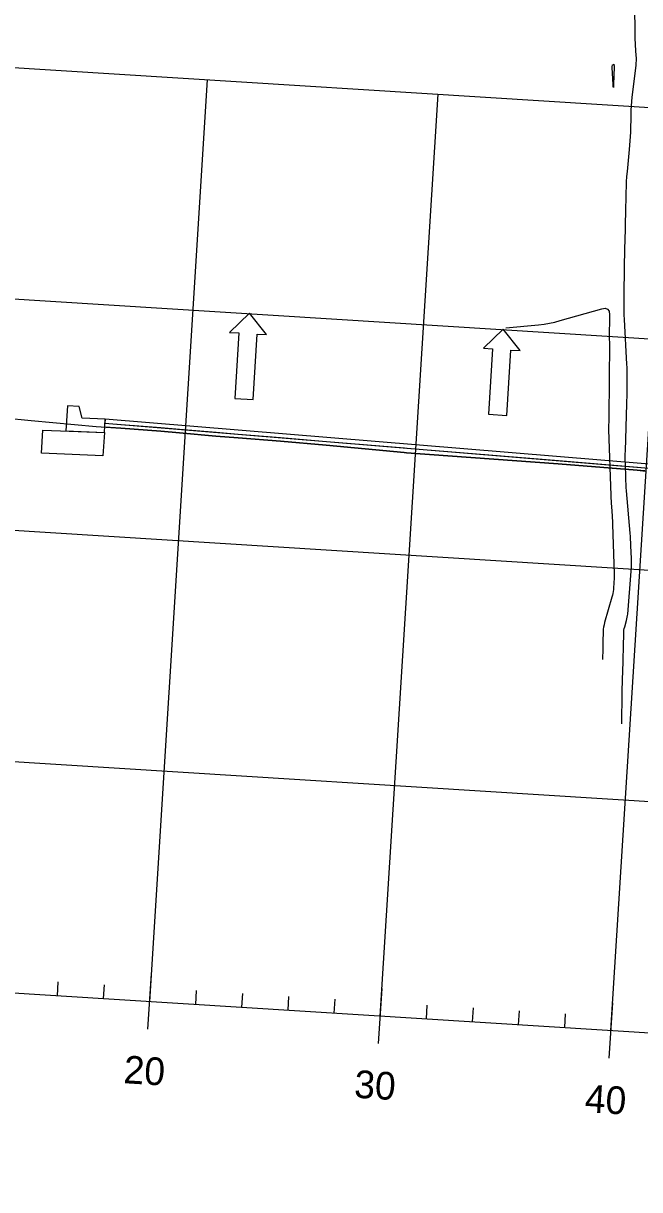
# Model space of a CAD drawing. Extents: x 658976 to 668726, y 639543 to 647196.
# Drawn here: x 661223.2 to 661356.5, y 641900.6 to 642153.2 of the extents above; entities that cross this region are included whole.
import ezdxf

# ---------------------------------------------------------------- set-up
doc = ezdxf.new("R2010")
doc.units = 0
for name, color, linetype in [('Ex_Minor Contours', 7, 'Continuous'), ('R_Axis', 7, 'Continuous'), ('R_Axis Annot', 7, 'Continuous'), ('R_Exist Surface', 7, 'Continuous'), ('R_Fin Surface', 7, 'Continuous'), ('R_Grid', 7, 'Continuous'), ('R_MOT', 7, 'Continuous'), ('R_Proposed Const Limits', 7, 'Continuous')]:
    doc.layers.add(name, color=color, linetype=linetype)

msp = doc.modelspace()

# ---------------------------------------------------------------- linework, layer by layer
msp.add_lwpolyline([(661240.88, 642067.45), (661235.89, 642067.67), (661235.21, 642070.22), (661232.71, 642070.37), (661232.37, 642064.9), (661240.7, 642064.54)], close=True)
at = {"layer": 'Ex_Minor Contours'}
for points in [[(661352.64, 642001.45), (661352.75, 642008.09), (661352.77, 642009.2), (661352.79, 642010.3), (661352.82, 642011.41), (661352.85, 642012.52), (661353.06, 642021.04), (661353.08, 642021.4), (661353.12, 642021.76), (661353.19, 642022.11), (661353.28, 642022.46), (661353.68, 642023.85), (661353.77, 642024.2), (661353.84, 642024.55), (661353.9, 642024.91), (661353.94, 642025.26), (661354.67, 642034.55), (661354.72, 642035.23), (661354.74, 642035.92), (661354.75, 642036.6), (661354.73, 642037.29), (661354.63, 642040.03), (661354.61, 642040.72), (661354.57, 642041.4), (661354.52, 642042.08), (661354.47, 642042.77), (661353.68, 642051.97), (661353.63, 642052.69), (661353.58, 642053.41), (661353.54, 642054.12), (661353.52, 642054.84), (661353.43, 642057.71), (661353.41, 642058.43), (661353.4, 642059.15), (661353.41, 642059.87), (661353.43, 642060.59), (661353.76, 642070.81), (661353.78, 642071.53), (661353.8, 642072.24), (661353.81, 642072.95), (661353.81, 642073.67), (661353.83, 642076.52), (661353.83, 642077.23), (661353.82, 642077.95), (661353.8, 642078.66), (661353.77, 642079.37), (661353.24, 642089.05), (661353.19, 642090.03), (661353.17, 642091), (661353.15, 642091.97), (661353.16, 642092.94), (661353.2, 642096.84), (661353.21, 642097.81), (661353.23, 642098.79), (661353.25, 642099.76), (661353.27, 642100.73), (661353.41, 642106.9), (661353.43, 642108.1), (661353.46, 642109.29), (661353.49, 642110.49), (661353.51, 642111.69), (661353.61, 642116.65), (661353.64, 642117.76), (661353.7, 642118.87), (661353.78, 642119.98), (661353.87, 642121.09), (661354.35, 642125.84), (661354.43, 642126.78), (661354.5, 642127.73), (661354.55, 642128.67), (661354.58, 642129.62), (661354.66, 642133.41), (661354.69, 642134.36), (661354.74, 642135.3), (661354.82, 642136.25), (661354.92, 642137.19), (661355.73, 642144.01), (661355.78, 642144.56), (661355.81, 642145.12), (661355.81, 642145.67), (661355.79, 642146.23), (661355.64, 642148.45), (661355.6, 642149), (661355.58, 642149.56), (661355.56, 642150.11), (661355.55, 642150.67), (661355.48, 642157.23)], [(661327.56, 642087.27), (661334.66, 642087.92), (661335.84, 642088.06), (661337, 642088.25), (661338.16, 642088.49), (661339.31, 642088.79), (661348.3, 642091.37), (661349.05, 642091.47), (661349.58, 642091.29), (661349.9, 642090.82), (661350, 642090.07), (661349.94, 642084.84), (661349.94, 642084.76), (661349.94, 642084.69), (661349.94, 642084.62), (661349.94, 642084.55), (661349.96, 642084.27), (661349.96, 642084.2), (661349.96, 642084.13), (661349.97, 642084.05), (661349.97, 642083.98), (661349.86, 642067.82), (661349.86, 642067.6), (661349.85, 642067.38), (661349.85, 642067.16), (661349.84, 642066.95), (661349.81, 642066.07), (661349.81, 642065.85), (661349.8, 642065.64), (661349.81, 642065.42), (661349.81, 642065.2), (661350.27, 642050.9), (661350.28, 642050.56), (661350.3, 642050.22), (661350.32, 642049.88), (661350.35, 642049.54), (661350.46, 642048.19), (661350.49, 642047.85), (661350.51, 642047.51), (661350.53, 642047.17), (661350.54, 642046.83), (661351, 642033.99), (661351.01, 642033.57), (661351, 642033.14), (661350.99, 642032.71), (661350.96, 642032.29), (661350.83, 642030.58), (661350.78, 642030.16), (661350.72, 642029.74), (661350.63, 642029.32), (661350.52, 642028.91), (661348.93, 642023.41), (661348.81, 642022.93), (661348.72, 642022.44), (661348.66, 642021.96), (661348.63, 642021.46), (661348.58, 642019.25), (661348.57, 642018.87), (661348.56, 642018.49), (661348.55, 642018.1), (661348.54, 642017.72), (661348.51, 642015.43)]]:
    msp.add_lwpolyline(points, dxfattribs=at)
msp.add_lwpolyline([(661350.82, 642144.22), (661350.84, 642144.23), (661350.85, 642144.24), (661350.87, 642144.26), (661350.92, 642144.34), (661350.94, 642144.36), (661350.94, 642144.36), (661350.95, 642144.35), (661350.95, 642144.33), (661350.98, 642143.88), (661350.98, 642143.87), (661350.98, 642143.86), (661350.98, 642143.85), (661350.98, 642143.84), (661350.98, 642143.8), (661350.98, 642143.79), (661350.98, 642143.77), (661350.98, 642143.76), (661350.98, 642143.75), (661350.89, 642139.91), (661350.88, 642139.44), (661350.85, 642139.28), (661350.82, 642139.43), (661350.79, 642139.91), (661350.55, 642143.59), (661350.55, 642143.65), (661350.55, 642143.71), (661350.56, 642143.77), (661350.57, 642143.83), (661350.66, 642144.14), (661350.66, 642144.16), (661350.67, 642144.18), (661350.69, 642144.19), (661350.71, 642144.19), (661350.8, 642144.21)], close=True, dxfattribs=at)
at = {"layer": 'R_Axis'}
for p, q in [((660402.17, 641994.63), (661899.22, 641900.61)), ((661250.12, 641935.36), (661250.87, 641947.34)), ((661230.54, 641942.6), (661230.72, 641945.6)), ((661240.52, 641941.98), (661240.7, 641944.97)), ((661300.02, 641932.23), (661300.77, 641944.2)), ((661260.48, 641940.72), (661260.66, 641943.72)), ((661270.46, 641940.1), (661270.64, 641943.09)), ((661280.44, 641939.47), (661280.63, 641942.46)), ((661290.42, 641938.84), (661290.61, 641941.84)), ((661310.38, 641937.59), (661310.57, 641940.58)), ((661320.36, 641936.96), (661320.55, 641939.96)), ((661330.34, 641936.33), (661330.53, 641939.33)), ((661349.92, 641929.09), (661350.68, 641941.07)), ((661340.32, 641935.71), (661340.51, 641938.7))]:
    msp.add_line(p, q, dxfattribs=at)
at = {"layer": 'R_Exist Surface'}
msp.add_lwpolyline([(661219.02, 642067.75), (661224.86, 642067.2), (661238.94, 642065.9), (661244.25, 642065.49), (661252.88, 642064.83), (661256.93, 642064.47), (661264.84, 642063.75), (661269.62, 642063.41), (661278.79, 642062.7), (661288.69, 642061.8), (661305.54, 642060.21), (661306.09, 642060.16), (661338.89, 642057.75), (661355.98, 642056.38), (661357.89, 642056.23)], dxfattribs=at)
at = {"layer": 'R_Fin Surface'}
msp.add_lwpolyline([(661357.63, 642056.25), (661355.98, 642056.38), (661338.89, 642057.75), (661306.09, 642060.16), (661305.54, 642060.21), (661288.69, 642061.8), (661278.79, 642062.7), (661269.62, 642063.41), (661264.84, 642063.75), (661256.93, 642064.47), (661252.88, 642064.83), (661244.25, 642065.49), (661240.78, 642065.76), (661240.83, 642066.62), (661244.3, 642066.33), (661252.93, 642065.62), (661256.98, 642065.28), (661264.89, 642064.63), (661269.67, 642064.23), (661278.84, 642063.47), (661288.75, 642062.65), (661305.61, 642061.25), (661306.16, 642061.2), (661338.94, 642058.49), (661356.03, 642057.07), (661357.67, 642056.93)], dxfattribs=at)
msp.add_lwpolyline([(661240.7, 642064.54), (661240.39, 642059.55), (661227.06, 642060.12), (661227.38, 642065.11)], close=True, dxfattribs=at)
at = {"layer": 'R_Grid'}
for p, q in [((660414.7, 642194.23), (661911.75, 642100.21)), ((660411.57, 642144.33), (661908.62, 642050.31)), ((661250.5, 641941.35), (661263.03, 642140.96)), ((661300.4, 641938.21), (661312.93, 642137.82)), ((661350.3, 641935.08), (661362.84, 642134.69)), ((660408.44, 642094.43), (661905.49, 642000.41)), ((660405.3, 642044.53), (661902.35, 641950.51)), ((660402.17, 641994.63), (661899.22, 641900.61))]:
    msp.add_line(p, q, dxfattribs=at)
at = {"layer": 'R_MOT'}
for p, q in [((661272.07, 642090.38), (661267.8, 642086.26)), ((661275.79, 642085.76), (661272.07, 642090.38)), ((661267.8, 642086.26), (661269.8, 642086.13)), ((661269.8, 642086.13), (661268.91, 642071.96)), ((661272.9, 642071.71), (661273.79, 642085.88)), ((661273.79, 642085.88), (661275.79, 642085.76)), ((661326.96, 642086.94), (661322.7, 642082.81)), ((661330.68, 642082.31), (661326.96, 642086.94)), ((661322.7, 642082.81), (661324.69, 642082.68)), ((661324.69, 642082.68), (661323.8, 642068.51)), ((661327.79, 642068.26), (661328.68, 642082.43)), ((661328.68, 642082.43), (661330.68, 642082.31)), ((661268.91, 642071.96), (661272.9, 642071.71)), ((661323.8, 642068.51), (661327.79, 642068.26))]:
    msp.add_line(p, q, dxfattribs=at)
at = {"layer": 'R_Proposed Const Limits'}
msp.add_lwpolyline([(661514.94, 642043.89), (661515, 642044.73), (661357.72, 642057.77), (661240.88, 642067.45), (661240.83, 642066.62), (661357.67, 642056.93)], close=True, dxfattribs=at)

# ---------------------------------------------------------------- texts
at = {"layer": 'R_Axis Annot'}
for s, p in [('20', (661244.73, 641923.68)), ('30', (661294.63, 641920.54)), ('40', (661344.53, 641917.41))]:
    msp.add_text(s, height=6, rotation=356.4063, dxfattribs=at).set_placement(p)

doc.saveas('drawing.dxf')
